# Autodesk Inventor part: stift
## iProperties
Created: 2004-12
Part Number: stift
Document SubType Name: Modeling
Designer: marocsikf
Manufacturer: Standard
Standards Organization: Custom
Author: marocsikf
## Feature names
1. Extrusion1
